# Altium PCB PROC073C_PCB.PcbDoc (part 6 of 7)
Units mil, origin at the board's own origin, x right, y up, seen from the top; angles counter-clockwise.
Board outline 2165.35 x 2695.12 mil, 8 copper layers (Top Layer, L2_GND, L3_SIGNAL 1, L4_SIGNAL 2, L5_SIGNAL 3, L6_SIGNAL 4, L7_GND, Bottom Layer), stack 55.9 mil thick; 393 components, 319 nets, 1311 pads, 1643 vias.
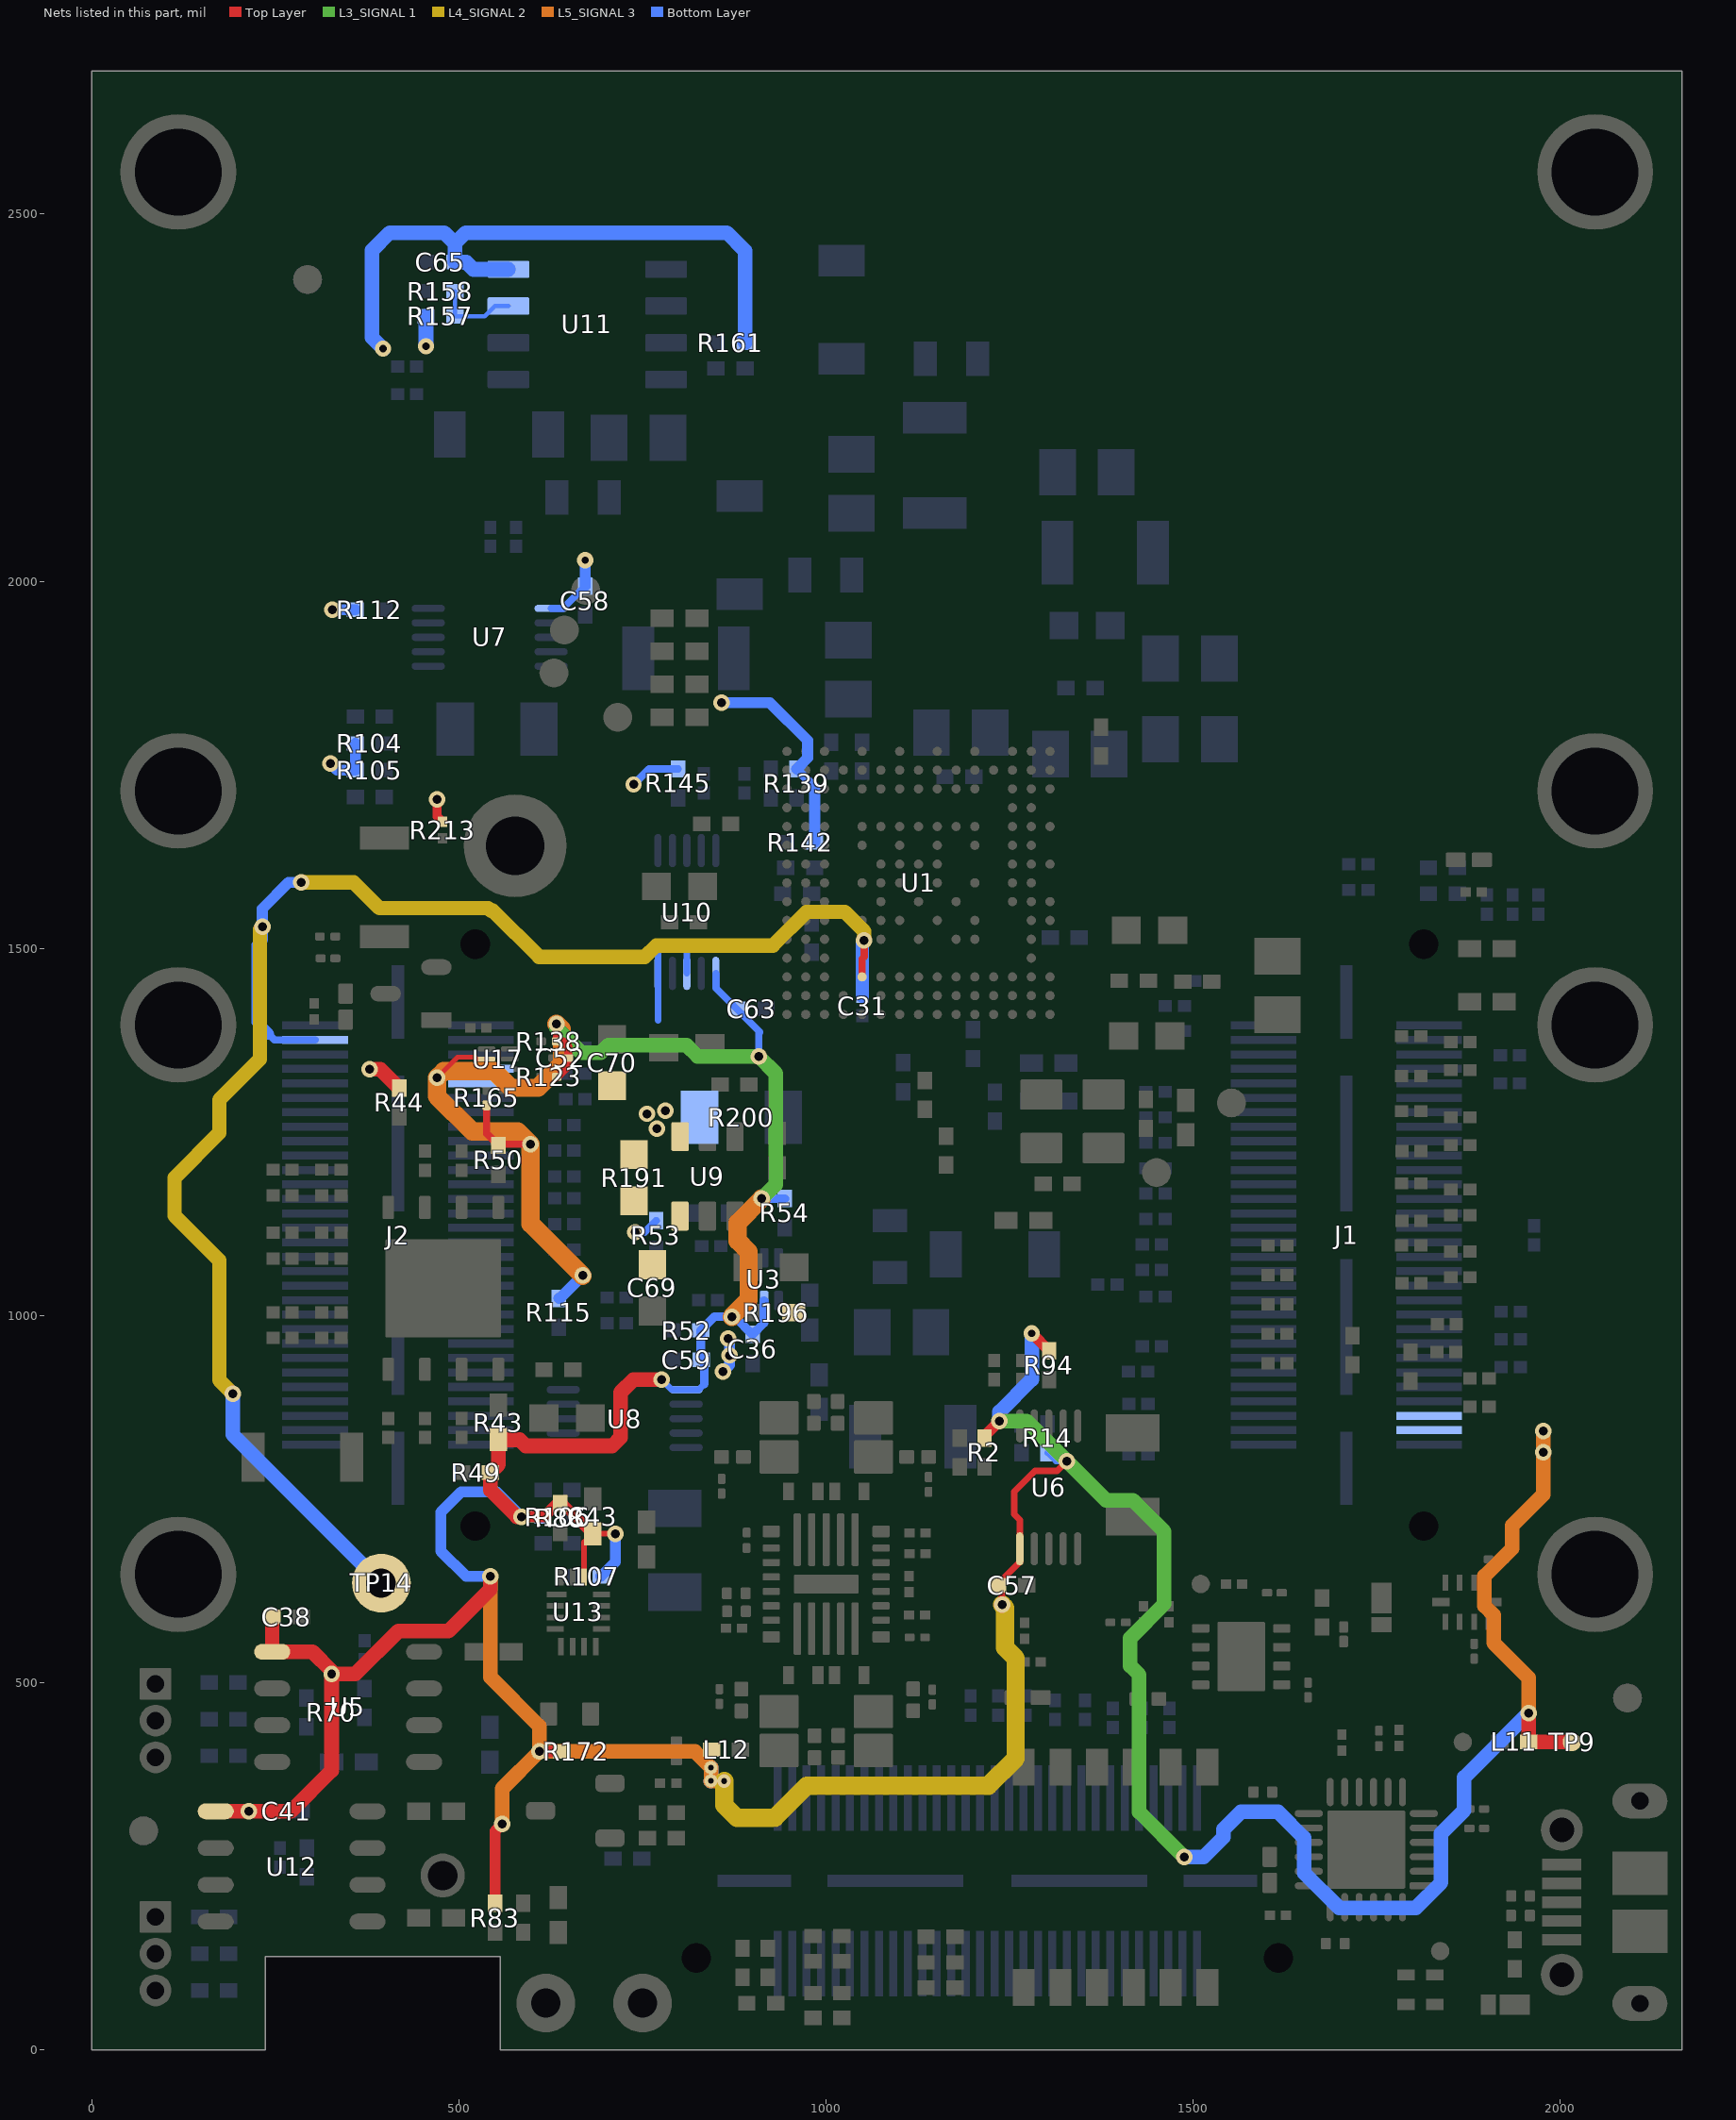
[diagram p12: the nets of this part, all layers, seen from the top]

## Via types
v1: diameter 13.77/15.74 (per signal layer), hole 5.9, Top Layer to L2_GND, tented both sides, 894 vias
v2: diameter 22.4, hole 12.2, Top Layer to Bottom Layer, tented both sides, 510 vias
v3: diameter 18, hole 8, Top Layer to Bottom Layer, tented both sides, 74 vias
v4: diameter 13.78/15.75 (per signal layer), hole 5.9, Top Layer to L2_GND, tented both sides, 72 vias
v5: diameter 22, hole 10, Top Layer to Bottom Layer, tented both sides, 61 vias
v6: diameter 19.68, hole 7.87, Top Layer to Bottom Layer, 16 vias
v7: diameter 13.77/15.74 (per signal layer), hole 5.9, Top Layer to L2_GND, tented top, 14 vias
v8: diameter 20, hole 10, Top Layer to Bottom Layer, tented both sides, 1 vias
v9: diameter 13.78/15.75 (per signal layer), hole 5.9, Top Layer to L2_GND, tented top, 1 vias

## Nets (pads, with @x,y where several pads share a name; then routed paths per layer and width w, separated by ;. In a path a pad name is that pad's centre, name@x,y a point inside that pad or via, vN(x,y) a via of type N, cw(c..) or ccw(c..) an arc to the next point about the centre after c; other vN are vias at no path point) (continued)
VCC_3V3: C36.2 C38.2 C41.2 C43.1 C52.2 C57.2 C58.2 C59.2 C63.2 C65.2 C69.1 J1.4 J1.6 J2.52 J2.54 L11.2 L12.1 R2.2 R14.2 R43.2 R44.2 R49.2 R50.1 R52.2 R53.2 R54.2 R70.1 R83.1 R88.2 R94.1 R104.2 R105.2 R106.2 R107.2 R112.1 R115.1 R123.1 R138.1 R139.2 R142.2 R145.1 R157.2 R161.2 R165.2 R172.2 R191.1 R213.2 TP9.1 U3.5 U5.5 U6.6 U7.6 U8.6 U9.1 U10.6 U11.8 U12.5 U13.14 U17.5 | length 9653.8
  Top Layer w6.69: v2(470.39,1323.91) 498.37,1351.89 521.97,1351.89 524.39,1349.48 U17.5@537.82,1349.48
  Top Layer w8: U13.14@670.66,644.19 670.66,691.58 C43.1@682.22,703.14 v2(713.13,703.14)
  Top Layer w9: v2(1239.72,606.43) 1239.72,626.9 C57.2@1233.87,632.76 1233.87,634.72 1263.99,664.84 U6.6@1263.99,682.61 1263.99,721.88 1256.27,729.6 1256.27,760.22 1284.73,788.68 1314.98,788.68 v2(1328.18,801.88)
  Top Layer w10: R165.2@537.82,1286.41 537.82,1247.93 R50.1@553.88,1231.88 555.61,1233.6 v2(597.7,1233.6)
  Top Layer w10.73: R123.1@633.25,1325.33 634.6,1325.33 649.03,1339.76 C52.2@649.03,1351.06 649.03,1367.16 642.57,1373.63 R138.1@633.25,1373.63 v2(633.25,1397.29)
  Top Layer w12: v2(470.62,1702.99) 470.62,1679.61 R213.2@477.94,1672.29
  Top Layer w15: R83.1@549.57,199.85 549.57,298.28 v2(559.11,307.82) ; v2(585.46,726.36) 615.64,726.36 633.67,744.38 R88.2@638.24,744.38 640.98,744.38 C43.1@682.22,703.14 ; v2(609.66,406.64) R172.2@640.13,406.64 ; R2.2@1214.31,833.59 1214.31,834.82 v2(1236.22,856.73) ; v5(1280.29,976.03) R94.1@1303.87,952.45
  Top Layer w19: U5.5@245.94,542.41 C38.2@245.94,589.74
  Top Layer w19.68: v2(1956.87,459.05) L11.2@1956.87,419.58 TP9.1@2015.61,419.58
  Top Layer w20: U12.5@169.09,325.13 v2(213.91,325.13) 271.3,325.13 326.89,380.72 v2(326.89,512.16) ; U5.5@245.94,542.41 300.81,542.41 326.89,516.33 v2(326.89,512.16) ; v2(378.7,1335.67) 393.13,1335.67 R44.2@418.88,1309.92 ; 542.96,762.7 543.25,762.42 ; v2(543.21,644.96) 543.21,627.89 486,570.68 417.69,570.68 359.17,512.16 v2(326.89,512.16) ; v2(585.46,726.36) 579.31,726.36 543.25,762.42 ; v2(776.27,913.04) 737.86,913.04 720.4,895.58 720.4,834.32 708.88,822.81 591.27,822.81 582.91,831.17 R43.2@553.88,831.17 553.88,797.27 R49.2@543.25,786.64 543.25,762.42
  L3_SIGNAL 1 w20: v2(633.25,1397.29) 633.25,1391.6 666.6,1358.24 693.11,1358.24 703.37,1368.5 809.96,1368.5 825.28,1353.18 v2(908.42,1353.18) 931.64,1329.96 931.64,1178.67 v2(912.43,1159.45) ; v2(1236.22,856.73) 1273.33,856.73 v2(1328.18,801.88) 1381.27,748.78 1417.89,748.78 1460.54,706.14 1460.54,607.41 1414.21,561.09 1414.21,523.36 1426.49,511.08 1426.49,324.24 v2(1487.9,262.82)
  L5_SIGNAL 3 w20: v2(543.21,644.96) 543.21,507.66 609.66,441.21 v2(609.66,406.64) ; v2(559.11,307.82) 559.11,356.09 v2(609.66,406.64) ; v3(843.24,366.57) v3@843.42,366.39 ; v3(861.42,366.39) v3@843.42,366.39 ; v2(1956.87,459.05) 1956.87,506.92 1909.31,554.48 1909.31,592.36 1896.69,604.98 1896.69,645.5 1934.57,683.39 1934.57,714.47 1976.48,756.38 v2(1976.48,813.88) v2(1976.48,842.87) ; v2(609.66,406.64) 821.54,406.64 v3(843.42,384.76) v3@843.42,366.39
  L5_SIGNAL 3 w25: v2(633.25,1397.29) 640.36,1390.18 640.36,1342.9 607.75,1310.29 571.09,1310.29 548.34,1333.04 479.52,1333.04 v2(470.39,1323.91) 470.39,1298.97 518.3,1251.06 580.24,1251.06 v2(597.7,1233.6) 597.7,1125.23 v2@668.45,1054.48 ; v2(871.67,998.68) 894.73,1021.74 894.73,1087.03 879.76,1102 879.76,1126.79 v2(912.43,1159.45)
  L4_SIGNAL 2 w25: v3(861.42,366.39) 861.42,333.66 878.85,316.23 930.21,316.23 974.02,360.04 1221.23,360.04 1258.27,397.08 1258.27,533.53 1243.94,547.87 1243.94,602.21 v2(1239.72,606.43)
  Bottom Layer w8: R14.2@1301.47,813.46 1313.05,801.88 v2(1328.18,801.88)
  Bottom Layer w9: v2(776.27,913.04) 790.04,899.27 U8.6@809.52,899.27 826.62,899.27 834.38,907.03
  Bottom Layer w9.84: U7.6@625.74,1963.11 641.76,1963.11 C58.2@672.08,1993.43
  Bottom Layer w10: v2(738,1723.37) 759.09,1744.45 R145.1@798.74,1744.46 ; v2(740.28,1113.77) 753.05,1113.77 R53.2@768.74,1129.46 ; U10.6@849.96,1466.11 849.96,1446.18 909.87,1386.27 908.42,1384.82 v2(908.42,1353.18)
  Bottom Layer w12: 834.38,907.03 834.38,935.7 C59.2@830,940.08 829.62,940.47 R52.2@829.62,980.11 848.19,998.68 v2(871.67,998.68) 875.77,998.68 C36.2@900,974.46 915.74,990.2 U3.5@915.74,1020.64 ; v2(912.43,1159.45) R54.2@943.74,1159.46 ; R139.2@960,1744.46 984.68,1719.77
  Bottom Layer w15: v2(213.91,325.13) C41.2@245.95,325.13 ; v2(325.17,1751.87) 334.15,1742.89 R105.2@359.16,1742.89 R104.2@359.16,1779.32 ; R70.1@326.89,479.59 v2(326.89,512.16) ; v2(327.89,1961.46) R112.1@359.16,1961.46 ; v2(543.21,644.96) 510.06,644.96 475.58,679.45 475.58,732.68 503.05,760.16 551.66,760.16 v2(585.46,726.36) R106.2@614.95,726.36 ; R115.1@636.16,1023.72 637.69,1023.72 v2(668.74,1054.77) ; C58.2@672.08,1993.43 v5(672.07,2028.74) ; R107.2@693.69,645.31 713.13,664.75 v2(713.13,703.14) ; v2(858,1834.77) 923.52,1834.77 975,1783.29 975,1759.45 R139.2@960,1744.46 ; R142.2@984.69,1644.77 984.68,1719.77
  Bottom Layer w20: v5(397,2316.77) 382,2331.77 382,2450.77 406,2474.77 480,2474.77 494.68,2460.08 ; v5(455.31,2320.08) R157.2@455.31,2360.77 ; U11.8@567.72,2424.77 520,2424.77 510,2434.77 C65.2@494.69,2434.77 494.68,2460.08 ; v3(843.24,366.57) 843.42,366.76 v3(843.42,384.76) ; R161.2@889.69,2324.77 889.68,2450.08 865,2474.77 509.37,2474.77 494.68,2460.08 ; v2(1236.22,856.73) 1236.22,869.08 1280.29,913.15 v5(1280.29,976.03) ; v2(1487.9,262.82) 1514.1,262.82 1541.5,290.22 1541.5,300.97 1564.9,324.38 1615.68,324.38 1650.86,289.19 1650.86,241.44 1698.72,193.59 1803,193.59 1837.58,228.17 1837.58,295.04 1869.09,326.55 1869.09,371.27 v2(1956.87,459.05)
VCC_LD_SW_3V3: C70.1 R191.2 R196.1 R200.1 U9.6 U10.8 U10.10 | length 224.1
  Bottom Layer w9: 771.22,1402.29 771.22,1497.77 781.22,1507.77 800.59,1507.77 810.59,1497.77 U10.8@810.59,1466.11
  Bottom Layer w15: v2(859.91,924.18) 868.76,933.03 v2(868.76,946.07) 868.76,966.98 v2(866.76,968.98)
  other v2: 770.05,1254.92 756.37,1274.97 781.23,1279.16
VPP_1P7: C31.2 J2.57 TP14.1 U1.L13 | length 2359.6
  Top Layer w10: U1.L13@1049.21,1461.43 1049.2,1486.11 1052.02,1488.93 v2(1052.02,1510.83)
  L4_SIGNAL 2 w19.68: v2(192.29,893.92) 173.92,912.28 173.92,1075.37 112.96,1136.33 112.96,1187.91 174.08,1249.03 174.08,1294.08 229.24,1349.25 229.24,1526.15 v2(232.52,1529.42) ; v2(285.39,1589.94) 357.04,1589.94 391.91,1555.06 540.25,1555.06 544.01,1551.31 546.65,1551.31 609.38,1488.58 753.41,1488.58 768.79,1503.96 927.62,1503.96 973.49,1549.83 1025.65,1549.83 1052.02,1523.45 v2(1052.02,1510.83)
  Bottom Layer w10: 241.12,1383.64 249.25,1375.52 J2.57@304.44,1375.52
  Bottom Layer w15: 241.12,1383.64 225,1399.77 225,1504.52 232.52,1512.04 v2(232.52,1529.42) 232.52,1554.21 268.24,1589.94 v2(285.39,1589.94)
  Bottom Layer w18: C31.2@1049.59,1434.76 1049.59,1508.39 v2(1052.02,1510.83)
  Bottom Layer w19.68: v2(192.29,893.92) 192.29,838.15 TP14.1@394.54,635.9
WP#: R157.1 R158.2 U11.7 | length 112.8
  Bottom Layer w6: R158.2@494.69,2394.77 R157.1@494.69,2360.77 535.43,2360.77 549.43,2374.77 U11.7@567.72,2374.77
pads on no net: FID1.1 FID2.1 FID3.1 FID4.1 FID5.1 FID6.1 J1.MH1 J1.MH2 J2.1 J2.2 J2.3 J2.4 J2.5 J2.6 J2.7 J2.8 J2.9 J2.10 J2.11 J2.12 J2.13 J2.14 J2.15 J2.16 J2.17 J2.18 J2.20 J2.22 J2.24 J2.26 J2.33 J2.35 J2.45 J2.47 J2.49 J2.51 J2.53 J2.55 J2.MH1 J2.MH2 J5.4 J6.4 J6.5 J6.6 J6.8 J6.14 J6.MH1 J6.MH2 LBL1.0 S1.6 S1.7 U2. U4. U11.1 U11.2 U14.10 U14.11 U14.14 U14.15 U14.16 U14.18 U14.19 U14.21 U14.22 U14.23 U14.24 U16.9@1565.44,511.07 U16.9@1565.44,560.68

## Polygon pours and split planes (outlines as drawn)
CONN_5V on Top Layer "CONN_5V_L01_P22319" (solid, remove dead copper, pour order 22319): 1077.37,317.76 1077.37,238.83 1095.58,220.62 1195.72,220.62 1251.48,164.86 1330.58,164.86 1380.08,115.35 1564.44,115.35 1604.25,155.16 1604.25,303.71 1570.7,337.26 1096.88,337.26
GND on Top Layer "GND_L01_P448" (solid, remove dead copper, pour order 22323): 33 vertices, not listed, extent 31,1503.77 2140,2673.82
GND on Top Layer "GND_L01_P22314" (solid, remove dead copper, pour order 22314): 27 vertices, not listed, extent 1134.79,431.41 1441.31,573.12
GND on Top Layer "TOP-No Net 1" (solid, remove dead copper, pour order 22322): 170,1130.18 160.59,1120.77 160.59,1101.95 170,1092.54 170,1013.41 170,737.08 207.5,699.58 207.5,557.27 200,549.78 30,549.95 30,2673.77 226,2673.77 226,1345.74 170,1289.74
RADAR_1V8 on Top Layer "RADAR_1V8_L01_P22244" (solid, remove dead copper, pour order 22244): 1031.46,939.5 1031.46,910.86 1036.01,906.31 1064.23,906.31 1069.98,912.06 1069.98,939.16 1065.03,944.12 1036.08,944.12
GND on Top Layer "TOP-No Net" (solid, remove dead copper, pour order 22320): 848.74,2673.73 667.78,2674.08 667.7,2057.81 727.62,1997.88 846.06,1997.88 848.74,2000.56
VCC_3V3 on Top Layer "TOP-No Net 1" (solid, remove dead copper, pour order 22311): 740.77,1036.27 779.97,1036.27 789.32,1045.61 789.32,1087.29 810.15,1108.12 816.25,1114.22 816.25,1154.98 791.46,1179.77 713.74,1179.77 713.74,1132.51 655.74,1074.5 655.74,1051.76 671.24,1036.26
RADAR_1V2 on Top Layer "TOP-No Net 1" (solid, remove dead copper, pour order 22293): 830.93,1414.77 860.59,1414.77 910.59,1364.77 955.59,1364.77 970.59,1349.77 970.59,1339.77 930.59,1299.77 885.59,1299.77 885.59,1334.76 875.59,1344.77 825.59,1344.77 820.59,1349.77 820.59,1404.43
GND on Top Layer " " (solid, remove dead copper, pour order 22284): 1018.78,524.15 1018.78,486.16 1030.58,474.37 1030.58,421.98 1024.32,415.72 975.98,415.72 971.57,420.14 971.57,472.14 982.09,482.66 982.09,523.95
5V_IN on Top Layer "5V_IN_L01_P22275" (solid, remove dead copper, pour order 22275): 17 vertices, not listed, extent 1251.55,516.39 1324.77,627.46
CB_PMIC_1V0 on Top Layer "CB_PMIC_1V0_L01_P22270" (solid, remove dead copper, pour order 22270): 1624.12,814.83 1575.25,814.83 1566.77,806.36 1566.77,770.14 1573.56,763.36 1623.52,763.36 1629.24,769.07 1629.24,809.7
CB_PMIC_1V2 on Top Layer "CB_PMIC_1V2_L01_P22268" (solid, remove dead copper, pour order 22268): 776.93,539.06 776.93,571.14 787.55,581.75 821.54,581.75 831.08,572.22 831.08,537.91 821.08,527.91 805.3,527.91 800.52,532.69 783.3,532.69
PMIC_1V2 on Top Layer "PMIC_1V2_L01_P22260" (solid, remove dead copper, pour order 22260): 731.77,764.34 723.76,772.35 723.76,794.24 740.26,810.74 774.84,810.74 781.89,803.69 781.89,785.03 761.2,764.34
RADAR_3V3 on Top Layer "RADAR_3V3_L01_P220" (solid, remove dead copper, pour order 22285): 815,1604.77 815,1524.77 820,1519.77 900,1519.77 905,1524.77 905,1539.77 890,1554.77 885,1554.77 865,1574.77 865,1594.77 855,1604.77
NetR214_1 on Top Layer "NETR214_1_L01_P22303" (solid, remove dead copper, pour order 22303): 428.73,1557.47 340.26,1557.47 324.8,1542.01 324.8,1471.04 332.41,1463.43 423.15,1463.43 453.32,1493.6 453.32,1532.88
CONN_5V on Top Layer "CONN_5V_L01_P22246" (solid, remove dead copper, pour order 22246): 1376.03,584.14 1373.52,581.63 1373.52,531.29 1378.52,526.29 1393,526.29 1398.96,532.25 1398.96,587.59 1395.12,591.44 1383.32,591.44
CONN_5V on Top Layer "CONN_5V_L01_P22274" (solid, remove dead copper, pour order 22274): 1605.95,570.98 1605.95,667.7 1616.86,678.6 1640.56,678.6 1656.71,662.46 1656.71,639.97 1637.57,620.84 1637.57,600.12 1632.56,595.11 1632.56,569.45 1630.35,567.25 1609.69,567.25
5V_IN_SW on Top Layer "5V_IN_SW_L01_P22289" (solid, remove dead copper, pour order 22289): 21 vertices, not listed, extent 1601.18,521.25 1739.18,601.39
NetD2_2 on Top Layer "NETD2_2_L01_P22292" (solid, remove dead copper, pour order 22292): 1656.71,629.15 1696.47,668.92 1770.38,668.92 1781.63,657.67 1781.63,602.91 1774.29,595.58 1741.54,595.58 1734.2,602.91 1663.55,602.91 1656.71,609.76
PMICOUT_3V3 on Top Layer "PMICOUT_3V3_L01_P22317" (solid, remove dead copper, pour order 22317): 26 vertices, not listed, extent 1236.39,339.84 1741.42,493.28
GND on Top Layer "GND_L01_P22304" (solid, remove dead copper, pour order 22304): 17 vertices, not listed, extent 902.3,105.41 1002.96,254.25
5V_IN on Top Layer "5V_IN_L01_P22283" (solid, remove dead copper, pour order 22283): 1781.52,590.62 1737.87,590.62 1722.9,575.65 1722.9,524.58 1736.24,511.24 1779.35,511.24 1791.8,523.7 1791.8,580.34
5V_IN_USB on Top Layer "5V_IN_USB_L01_P22276" (solid, remove dead copper, pour order 22276): 18 vertices, not listed, extent 1602.23,459.15 1722.05,532.03
PMIC_3V3 on Top Layer "Bottom Layer-PMIC_3V3" (solid, pour order 22306): 871.36,389.15 880.03,380.48 880.03,333.59 883.52,330.1 963.71,330.1 995.6,361.99 995.6,432.05 871.36,432.05
CB_PMIC_1V8 on Top Layer "CB_PMIC_1V8_L01_P22288" (solid, remove dead copper, pour order 22288): 937.54,1087.93 990.48,1087.93 999.69,1097.14 1033.26,1097.14 1040.77,1089.63 1040.77,1041.71 1025.44,1026.37 996.45,1026.37 980.42,1042.4 936.76,1042.4 933.18,1045.98 933.18,1083.57
VCC_LD_SW_3V3 on Top Layer "VCC_LD_SW_3V3_L01_P22294" (solid, remove dead copper, pour order 22294): 936.29,1023.35 936.29,999.84 917.45,981 853.41,981 848.47,976.06 848.47,917.08 857.82,907.73 875.53,907.73 890.04,922.24 907.46,939.66 961.46,939.66 985.9,964.11 985.9,1026.72 979.93,1032.7 945.63,1032.7
PMIC_1V8 on Top Layer "PMIC_1V8_L01_P22312" (solid, remove dead copper, pour order 22312): 17 vertices, not listed, extent 1289.77,606.39 1467.93,755.32
VCC_LD_SW_3V3 on Top Layer "TOP-No Net 1" (solid, remove dead copper, pour order 22308): 691.74,1335.77 767.73,1335.77 813.74,1289.77 813.74,1224.77 788.74,1199.77 718.74,1199.77 708.74,1209.77 708.74,1245.77 686.74,1267.77 686.74,1330.77
RADAR_3V3 on Top Layer "RADAR_3V3_L01_P210" (solid, remove dead copper, pour order 22269): 1102.98,1262.77 1157,1262.77 1169,1262.77 1174,1257.77 1174,1235.77 1171,1232.76 1148,1232.77 1133.18,1217.94 1111.82,1217.94 1094,1235.77 1094,1253.78
5V_IN on Top Layer "Bottom Layer-5V_IN 4" (solid, pour order 22250): 916.33,779.48 916.33,738.48 956.33,738.48 958.33,740.48 958.33,776.48 955.33,779.48
GND on Top Layer "TOP-No Net 11" (solid, remove dead copper, pour order 22296): 94 vertices, not listed, extent 996.99,1979.09 1095.41,2452.08
PMIC_1V0 on Top Layer "Bottom Layer-PMIC_1V0 1" (solid, pour order 22307): 960.52,839.43 960.52,871.68 994.13,871.68 994.13,931.27 847.15,931.27 847.15,839.43
5V_IN_USB on Top Layer "5V_IN_USB_L01_P22310" (solid, remove dead copper, pour order 22310): 1875.54,86.33 1880.49,81.38 1909.52,81.38 1921.49,69.42 1921.49,48.85 1900.75,28.12 1673.31,28.12 1662.82,38.61 1662.82,69.95 1703.04,110.18 1730.7,110.18 1754.55,86.33
PMICOUT_3V3 on Top Layer "PMICOUT_3V3_L01_P22315" (solid, remove dead copper, pour order 22315): 19 vertices, not listed, extent 1773.63,296.73 1930.87,488.17
CB_PMIC_1V8 on Top Layer "CB_PMIC_1V8_L01_P22318" (solid, remove dead copper, pour order 22318): 17 vertices, not listed, extent 1305.39,644.91 1729.65,918.05
GND on Top Layer "TOP-No Net 1" (solid, remove dead copper, pour order 22290): 707.44,1015.04 723.12,1030.72 789.62,1030.72 795.85,1024.49 795.85,967.98 775.02,947.16 720.05,947.16 707.44,959.76
VCC_3V3 on Top Layer " " (solid, remove dead copper, pour order 22261): 860.94,381.7 873.35,369.28 873.35,358.04 868.31,353 829.37,353 829.37,421.73 860.94,421.73
PMIC_1V2 on Top Layer "Bottom Layer-PMIC_1V2" (solid, pour order 22309): 1172.84,448.01 1172.84,359.84 1006.53,359.83 1006.53,448.01
5V_IN on Top Layer "Bottom Layer-5V_IN 1" (solid, pour order 22247): 916.33,528.98 916.33,487.98 956.33,487.98 958.33,489.98 958.33,525.98 955.33,528.98
5V_IN on Top Layer "Bottom Layer-5V_IN 3" (solid, pour order 22249): 1084.33,739.98 1084.33,780.98 1044.33,780.98 1042.33,778.98 1042.33,742.98 1045.33,739.98
5V_IN on Top Layer "Bottom Layer-5V_IN 2" (solid, pour order 22248): 1084.33,489.48 1084.33,530.48 1044.33,530.48 1042.33,528.48 1042.33,492.48 1045.33,489.48
PMIC_1V8 on Top Layer "Bottom Layer-PMIC_1V8" (solid, pour order 22313): 1004.7,885.77 1004.7,954.5 1020.66,970.46 1148.01,970.46 1163.6,954.87 1163.6,889.45 1163.6,837.48 1036.52,837.48 1036.52,870.9 1004.7,870.9
GND on Top Layer " " (solid, remove dead copper, pour order 22287): 1016.81,745.5 982.84,745.5 981.72,746.62 981.72,783.53 973.88,791.37 973.88,862.62 975.87,864.6 1025.45,864.6 1028.19,861.86 1028.19,790.2 1017.93,779.95 1017.93,747.74
PMICOUT_3V3 on Top Layer "PMICOUT_3V3_L01_P22286" (solid, remove dead copper, pour order 22286): 581,2045.4 581,1980.02 592.26,1968.76 629.35,1968.76 651.94,1991.35 651.94,2039.93 636.02,2055.85 591.45,2055.85
RADAR_1V8 on Top Layer "RADAR_1V8_L01_P222" (solid, remove dead copper, pour order 22291): 1572.86,1459.28 1575.38,1456.77 1587.99,1456.77 1590.66,1454.1 1637.41,1454.1 1648.54,1442.96 1648.54,1381.73 1643.18,1376.37 1578.77,1376.37 1555.96,1399.18 1555.96,1453.47 1561.77,1459.28
GND on Top Layer "TOP-No Net" (solid, remove dead copper, pour order 22316): 1976.7,2635.77 1976.77,2673.69 809.74,2673.83 809.74,2635.77
GND on Top Layer "TOP-No Net 17" (solid, remove dead copper, pour order 22297): 94 vertices, not listed, extent 1193.85,1979.09 1292.27,2452.08
GND on Top Layer "OUTLINE-No Net" (solid, remove dead copper, pour order 22259): 1787.47,2046.12 1787.47,1990.83 1805.98,1990.83 1805.98,1979.11 1821.73,1979.11 1821.73,2006.58 1803.22,2006.58 1803.22,2030.38 1821.73,2030.38 1821.73,2071.23 1805.98,2071.23 1805.98,2046.12 1787.47,2046.12
TX3 on Top Layer "TOP-RX1 72" (solid, pour order 22221): 1835.62,2249.46 1831.62,2249.46 1831.62,2188.91 1835.62,2188.91 1835.62,2249.46
GND on Top Layer "OUTLINE-No Net" (solid, remove dead copper, pour order 22255): 1894.77,2452.1 1772.47,2452.1 1772.47,2436.35 1894.77,2436.35 1894.77,2452.1
TX3 on Top Layer "TOP-RX1 73" (solid, pour order 22222): 1835.62,2358.05 1831.62,2358.05 1831.62,2297.49 1835.62,2297.49 1835.62,2358.05
GND on Top Layer "TOP-GND 25" (solid, remove dead copper, pour order 22239): 1894.77,2110.6 1845.52,2110.6 1845.52,2094.86 1894.77,2094.86
TX3 on Top Layer "TOP-RX1 74" (solid, pour order 22225): 1837.52,2071.23 1829.73,2071.23 1829.73,2033.05 1837.52,2033.05 1837.52,2071.23
GND on Top Layer "OUTLINE-No Net" (solid, remove dead copper, pour order 22241): 1821.73,2110.6 1772.47,2110.6 1772.47,2094.86 1821.73,2094.86 1821.73,2110.6
TX3 on Top Layer "TOP-RX1 75" (solid, pour order 22209): 1837.52,2033.05 1829.73,2033.05 1829.73,2018.48 1837.52,2018.48 1837.52,2033.05
GND on Top Layer "OUTLINE-No Net" (solid, remove dead copper, pour order 22236): 1821.73,2094.86 1805.98,2094.86 1805.98,2071.23 1821.73,2071.23 1821.73,2094.86
TX3 on Top Layer "TOP-RX1 76" (solid, pour order 22206): 1850.51,2036.94 1837.52,2036.94 1837.52,2029.15 1850.51,2029.15 1850.51,2036.94
GND on Top Layer "TOP-GND 26" (solid, remove dead copper, pour order 22234): 1861.27,2094.86 1845.52,2094.86 1845.52,2071.23 1861.27,2071.23 1861.27,2094.86
TX3 on Top Layer "TOP-RX1 77" (solid, pour order 22264): 1859.21,2188.91 1808.03,2188.91 1808.03,2140.88 1859.21,2140.88 1859.21,2188.91
GND on Top Layer "TOP-GND 27" (solid, remove dead copper, pour order 22251): 1861.27,2071.23 1845.52,2071.23 1845.52,2044.94 1858.51,2044.94 1858.51,2021.15 1845.52,2021.15 1845.52,1979.11 1861.27,1979.11 1861.27,2005.4 1874.26,2005.4 1874.26,2060.69 1861.27,2060.69 1861.27,2071.23
TX3 on Top Layer "TOP-RX1 78" (solid, pour order 22230): 1837.52,2110.6 1829.73,2110.6 1829.73,2071.23 1837.52,2071.23 1837.52,2110.6
TX3 on Top Layer "TOP-RX1 79" (solid, pour order 22213): 1835.62,2140.88 1831.62,2140.88 1831.62,2110.6 1835.62,2110.6 1835.62,2140.88
TX3 on Top Layer "TOP-RX1 80" (solid, pour order 22215): 1829.73,2022.38 1811.22,2022.38 1811.22,2014.58 1829.73,2014.58 1829.73,2022.38
TX3 on Top Layer "TOP-RX1 81" (solid, pour order 22271): 1871.02,2297.49 1796.22,2297.49 1796.22,2249.46 1871.02,2249.46 1871.02,2297.49
GND on Top Layer "OUTLINE-No Net" (solid, remove dead copper, pour order 22278): 1788.22,2436.35 1772.47,2436.35 1772.47,2110.6 1788.22,2110.6 1788.22,2436.35
TX3 on Top Layer "TOP-RX1 83" (solid, pour order 22263): 1859.21,2406.08 1808.03,2406.08 1808.03,2358.05 1859.21,2358.05 1859.21,2406.08
GND on Top Layer "OUTLINE-No Net" (solid, remove dead copper, pour order 22281): 1894.77,2436.35 1879.02,2436.35 1879.02,2110.6 1894.77,2110.6 1894.77,2436.35
GND on Top Layer "OUTLINE-No Net" (solid, remove dead copper, pour order 22282): 1697.92,2534.78 1682.17,2534.78 1682.17,2209.03 1697.92,2209.03 1697.92,2534.78
TX2 on Top Layer "TOP-RX1 83" (solid, pour order 22265): 1662.36,2504.5 1611.18,2504.5 1611.18,2456.47 1662.36,2456.47 1662.36,2504.5
GND on Top Layer "OUTLINE-No Net" (solid, remove dead copper, pour order 22277): 1591.37,2534.78 1575.62,2534.78 1575.62,2209.03 1591.37,2209.03 1591.37,2534.78
TX2 on Top Layer "TOP-RX1 81" (solid, pour order 22273): 1674.17,2395.92 1599.37,2395.92 1599.37,2347.89 1674.17,2347.89 1674.17,2395.92
TX2 on Top Layer "TOP-RX1 80" (solid, pour order 22214): 1632.88,2120.8 1614.37,2120.8 1614.37,2113.01 1632.88,2113.01 1632.88,2120.8
TX2 on Top Layer "TOP-RX1 79" (solid, pour order 22212): 1638.77,2239.3 1634.77,2239.3 1634.77,2209.03 1638.77,2209.03 1638.77,2239.3
TX2 on Top Layer "TOP-RX1 78" (solid, pour order 22228): 1640.67,2209.03 1632.88,2209.03 1632.88,2169.66 1640.67,2169.66 1640.67,2209.03
TX2 on Top Layer "TOP-RX1 77" (solid, pour order 22267): 1662.36,2287.34 1611.18,2287.34 1611.18,2239.3 1662.36,2239.3 1662.36,2287.34
GND on Top Layer "TOP-GND 26" (solid, remove dead copper, pour order 22233): 1664.42,2193.28 1648.67,2193.28 1648.67,2169.66 1664.42,2169.66 1664.42,2193.28
TX2 on Top Layer "TOP-RX1 76" (solid, pour order 22207): 1653.66,2135.37 1640.67,2135.37 1640.67,2127.57 1653.66,2127.57 1653.66,2135.37
GND on Top Layer "OUTLINE-No Net" (solid, remove dead copper, pour order 22235): 1624.88,2193.28 1609.13,2193.28 1609.13,2169.66 1624.88,2169.66 1624.88,2193.28
TX2 on Top Layer "TOP-RX1 75" (solid, pour order 22210): 1640.67,2131.47 1632.88,2131.47 1632.88,2116.9 1640.67,2116.9 1640.67,2131.47
GND on Top Layer "OUTLINE-No Net" (solid, remove dead copper, pour order 22238): 1624.88,2209.03 1575.62,2209.03 1575.62,2193.28 1624.88,2193.28 1624.88,2209.03
TX2 on Top Layer "TOP-RX1 74" (solid, pour order 22223): 1640.67,2169.66 1632.88,2169.66 1632.88,2131.47 1640.67,2131.47 1640.67,2169.66
GND on Top Layer "TOP-GND 25" (solid, remove dead copper, pour order 22240): 1697.92,2209.03 1648.67,2209.03 1648.67,2193.28 1697.92,2193.28 1697.92,2209.03
TX2 on Top Layer "TOP-RX1 73" (solid, pour order 22218): 1638.77,2456.47 1634.77,2456.47 1634.77,2395.92 1638.77,2395.92 1638.77,2456.47
GND on Top Layer "OUTLINE-No Net" (solid, remove dead copper, pour order 22254): 1697.92,2550.53 1575.62,2550.53 1575.62,2534.78 1697.92,2534.78 1697.92,2550.53
TX2 on Top Layer "TOP-RX1 72" (solid, pour order 22219): 1638.77,2347.89 1634.77,2347.89 1634.77,2287.34 1638.77,2287.34 1638.77,2347.89
GND on Top Layer "OUTLINE-No Net" (solid, remove dead copper, pour order 22258): 1393.77,2046.12 1393.77,1990.83 1412.28,1990.83 1412.28,1979.11 1428.02,1979.11 1428.02,2006.58 1409.52,2006.58 1409.52,2030.38 1428.02,2030.38 1428.02,2071.23 1412.28,2071.23 1412.28,2046.12 1393.77,2046.12
TX1 on Top Layer "TOP-RX1 72" (solid, pour order 22217): 1441.92,2249.46 1437.92,2249.46 1437.92,2188.91 1441.92,2188.91 1441.92,2249.46
GND on Top Layer "OUTLINE-No Net" (solid, remove dead copper, pour order 22256): 1501.07,2452.1 1378.77,2452.1 1378.77,2436.35 1501.07,2436.35 1501.07,2452.1
TX1 on Top Layer "TOP-RX1 73" (solid, pour order 22220): 1441.92,2358.05 1437.92,2358.05 1437.92,2297.49 1441.92,2297.49 1441.92,2358.05
GND on Top Layer "TOP-GND 25" (solid, remove dead copper, pour order 22242): 1501.07,2110.6 1451.82,2110.6 1451.82,2094.86 1501.07,2094.86 1501.07,2110.6
TX1 on Top Layer "TOP-RX1 74" (solid, pour order 22224): 1443.82,2071.23 1436.02,2071.23 1436.02,2033.05 1443.82,2033.05 1443.82,2071.23
GND on Top Layer "OUTLINE-No Net" (solid, remove dead copper, pour order 22243): 1428.02,2110.6 1378.77,2110.6 1378.77,2094.86 1428.02,2094.86 1428.02,2110.6
TX1 on Top Layer "TOP-RX1 75" (solid, pour order 22208): 1443.82,2033.05 1436.02,2033.05 1436.02,2018.48 1443.82,2018.48 1443.82,2033.05
GND on Top Layer "OUTLINE-No Net" (solid, remove dead copper, pour order 22232): 1428.02,2094.86 1412.28,2094.86 1412.28,2071.23 1428.02,2071.23 1428.02,2094.86
TX1 on Top Layer "TOP-RX1 76" (solid, pour order 22205): 1456.81,2036.94 1443.82,2036.94 1443.82,2029.15 1456.81,2029.15 1456.81,2036.94
GND on Top Layer "TOP-GND 26" (solid, remove dead copper, pour order 22237): 1467.57,2094.86 1451.82,2094.86 1451.82,2071.23 1467.57,2071.23 1467.57,2094.86
TX1 on Top Layer "TOP-RX1 77" (solid, pour order 22262): 1465.51,2188.91 1414.33,2188.91 1414.33,2140.88 1465.51,2140.88 1465.51,2188.91
GND on Top Layer "TOP-GND 27" (solid, remove dead copper, pour order 22252): 1467.57,2071.23 1451.82,2071.23 1451.82,2044.94 1464.81,2044.94 1464.81,2021.15 1451.82,2021.15 1451.82,1979.11 1467.57,1979.11 1467.57,2005.4 1480.56,2005.4 1480.56,2060.69 1467.57,2060.69 1467.57,2071.23
TX1 on Top Layer "TOP-RX1 78" (solid, pour order 22231): 1443.82,2110.6 1436.02,2110.6 1436.02,2071.23 1443.82,2071.23 1443.82,2110.6
TX1 on Top Layer "TOP-RX1 79" (solid, pour order 22211): 1441.92,2140.88 1437.92,2140.88 1437.92,2110.6 1441.92,2110.6 1441.92,2140.88
TX1 on Top Layer "TOP-RX1 80" (solid, pour order 22216): 1436.02,2022.38 1417.52,2022.38 1417.52,2014.58 1436.02,2014.58 1436.02,2022.38
TX1 on Top Layer "TOP-RX1 81" (solid, pour order 22272): 1477.32,2297.49 1402.52,2297.49 1402.52,2249.46 1477.32,2249.46 1477.32,2297.49
GND on Top Layer "OUTLINE-No Net" (solid, remove dead copper, pour order 22279): 1394.52,2436.35 1378.77,2436.35 1378.77,2110.6 1394.52,2110.6 1394.52,2436.35
TX1 on Top Layer "TOP-RX1 83" (solid, pour order 22266): 1465.51,2406.08 1414.33,2406.08 1414.33,2358.05 1465.51,2358.05 1465.51,2406.08
GND on Top Layer "OUTLINE-No Net" (solid, remove dead copper, pour order 22280): 1501.07,2436.35 1485.32,2436.35 1485.32,2110.6 1501.07,2110.6 1501.07,2436.35
GND on Top Layer "TOP-No Net 10" (solid, remove dead copper, pour order 22295): 94 vertices, not listed, extent 1095.42,1979.09 1193.84,2452.08
GND on Top Layer "TOP-No Net 23" (solid, remove dead copper, pour order 22305): 125 vertices, not listed, extent 891.67,1979.09 996.98,2452.08
GND on Top Layer "TOP-No Net 24" (solid, pour order 22245): 35 vertices, not listed, extent 1292.28,2094.9 1299.17,2452.08
RX1 on Top Layer "TOP-No Net 43" (solid, remove dead copper, pour order 22301): 38 vertices, not listed, extent 910.37,1979.09 985.17,2406.06
RX2 on Top Layer "TOP-No Net 42" (solid, remove dead copper, pour order 22299): 38 vertices, not listed, extent 1008.8,1979.09 1083.6,2406.06
RX3 on Top Layer "TOP-No Net 41" (solid, remove dead copper, pour order 22300): 38 vertices, not listed, extent 1107.23,1979.09 1182.03,2406.06
RX4 on Top Layer "TOP-No Net 40" (solid, remove dead copper, pour order 22298): 38 vertices, not listed, extent 1205.66,1979.09 1280.46,2406.06
TX1 on Top Layer "TOP-RX1 82" (solid, remove dead copper, pour order 22229): 1443.82,2018.48 1436.02,2018.48 1436.02,1979.11 1443.82,1979.11 1443.82,2018.48
GND on Top Layer "OUTLINE-No Net" (solid, remove dead copper, pour order 22257): 1590.62,2144.55 1590.62,2089.26 1609.13,2089.26 1609.13,2077.53 1624.88,2077.53 1624.88,2105.01 1606.37,2105.01 1606.37,2128.8 1624.88,2128.8 1624.88,2169.66 1609.13,2169.66 1609.13,2144.55 1590.62,2144.55
GND on Top Layer "TOP-GND 27" (solid, remove dead copper, pour order 22253): 1664.42,2169.66 1648.67,2169.66 1648.67,2143.37 1661.66,2143.37 1661.66,2119.57 1648.67,2119.57 1648.67,2077.53 1664.42,2077.53 1664.42,2103.82 1677.41,2103.82 1677.41,2159.12 1664.42,2159.12 1664.42,2169.66
TX2 on Top Layer "TOP-RX1 82" (solid, remove dead copper, pour order 22226): 1640.67,2116.9 1632.88,2116.9 1632.88,2077.53 1640.67,2077.53 1640.67,2116.9
TX3 on Top Layer "TOP-RX1 82" (solid, remove dead copper, pour order 22227): 1837.52,2018.48 1829.73,2018.48 1829.73,1979.11 1837.52,1979.11 1837.52,2018.48
RADAR_VOUT_PA on Top Layer "TOP-No Net 1" (solid, remove dead copper, pour order 22302): 17 vertices, not listed, extent 1271.59,1735.77 1484.59,1849.77
GND on Top Layer "TOP-No Net" (solid, remove dead copper, pour order 22321): 1940.79,2673.65 2139.97,2674.05 2140.06,1916.77 1940.79,1916.76
GND on L3_SIGNAL 1 "GND_L03_P3050" (solid, remove dead copper, pour order 22329): 1013.99,1633.78 1079,1568.77 1079,1546.21 1166.44,1458.77 1315,1458.77 1399,1542.77 1619.2,1542.77 1710,1633.57 1710,1951.77 1620,2041.77 1089,2041.77 1013.99,1966.76
RADAR_1V2 on L3_SIGNAL 1 "RADAR_1V2_L03_P2940" (solid, remove dead copper, pour order 22327): 18 vertices, not listed, extent 662.15,1333.29 1182.6,2011.77
5V_IN on L3_SIGNAL 1 "5V_IN_L03_P22328" (solid, remove dead copper, pour order 22328): 1642.6,703.75 1809.3,870.44 1928.77,870.44 1957.87,841.34 1957.87,550.26 1982.89,525.25 2030.98,525.25 2097.36,458.88 2097.36,86.6 2030.42,19.66 1682.03,19.66 1642.6,59.09
5V_IN on L3_SIGNAL 1 "5V_IN_L03_P22326" (solid, remove dead copper, pour order 22326): 1104.05,800.65 1178.88,800.65 1283.63,695.9 1320.16,659.37 1320.16,553.76 1239.83,473.43 934.33,473.43 912.61,495.15 912.61,770.58 942.68,800.65
GND on L3_SIGNAL 1 "RADAR_1V8_L01_P-001" (solid, remove dead copper, pour order 22331): 25 vertices, not listed, extent 30,549.63 2140,2673.77
CB_PMIC_1V2 on L3_SIGNAL 1 "CB_PMIC_1V2_L03_P22330" (solid, remove dead copper, pour order 22330): 34 vertices, not listed, extent 229.92,488.7 908.93,2369.41
CONN_5V on L3_SIGNAL 1 "CONN_5V_L03_P22325" (solid, remove dead copper, pour order 22325): 897.63,88.44 897.63,127.1 729.1,295.63 660.14,295.63 626.99,262.49 626.99,41.5 652.99,15.51 824.7,15.51
GND on L5_SIGNAL 3 "GND_L05_P22338" (solid, remove dead copper, pour order 22338): 42 vertices, not listed, extent 1148.42,27.25 1866.73,1408.39
5V_IN_USB on L5_SIGNAL 3 "5V_IN_USB_L05_P22336" (solid, remove dead copper, pour order 22336): 1569.35,26.26 1569.35,384.02 1643.42,458.09 1643.42,478.44 1682.03,517.05 1682.03,582.2 1738.13,638.3 1844.76,638.3 1893.66,589.39 1893.66,576.15 1893.66,62.25 1857.66,26.26
GND on L5_SIGNAL 3 "BOTTOM-No Net" (solid, remove dead copper, pour order 22342): 31 vertices, not listed, extent 30,549.77 2140,2673.77
RADAR_1V8 on L5_SIGNAL 3 "RADAR_1V8_L04_P3008" (solid, remove dead copper, pour order 22337): 23 vertices, not listed, extent 882.64,1354.77 1582.52,1814.95
5V_IN on L5_SIGNAL 3 "5V_IN_L05_P22341" (solid, remove dead copper, pour order 22341): 23 vertices, not listed, extent 589.92,23.49 1602.31,624.2
PMIC_1V0 on L5_SIGNAL 3 "PMIC_1V0_L04_P2966" (solid, remove dead copper, pour order 22334): 681.23,1491.64 681.23,1835.66 653.12,1863.77 570.19,1863.77 493.58,1863.77 379.33,1749.52 379.32,1374.27 437.18,1316.42 648.32,1316.42 718.63,1386.73 718.63,1454.25
VCC_3V3 on L5_SIGNAL 3 "VCC_3V3_L04_P2992" (solid, remove dead copper, pour order 22339): 490.76,1872.91 635.08,1872.91 642.16,1865.83 642.16,1728.22 677.33,1693.05 822.28,1693.05 850.28,1693.05 891.28,1734.04 891.28,2248.57 802,2338.77 328,2338.77 261,2271.77 261,1770 293.01,1737.99 355.84,1737.99
CB_PMIC_1V8 on L5_SIGNAL 3 "CB_PMIC_1V8_L05_P22335" (solid, remove dead copper, pour order 22335): 35 vertices, not listed, extent 895.66,632.16 1700.13,1106.65
RADAR_1V2 on L5_SIGNAL 3 "RADAR_1V2_L05_P22333" (solid, remove dead copper, pour order 22333): 21 vertices, not listed, extent 767.92,1324.1 1039.56,1706.57
CONN_5V on L5_SIGNAL 3 "CONN_5V_L05_P22340" (solid, remove dead copper, pour order 22340): 30 vertices, not listed, extent 162.19,153.41 712.31,1523.69
PMIC_1V0 on L5_SIGNAL 3 "PMIC_1V0_L05_P22332" (solid, remove dead copper, pour order 22332): 1048.57,801.11 1041.25,793.8 1041.25,724.26 1008.83,691.84 862.05,691.84 842.56,711.33 842.56,883.58 884.58,925.6 955.79,925.6 970.91,910.48 970.91,893.47 999.43,864.95 1024.43,864.95 1048.57,840.81
5V_IN_USB on Bottom Layer "5V_IN_USB_L08_P22366" (solid, remove dead copper, pour order 22366): 17 vertices, not listed, extent 1670.87,460.03 1717.09,505.28
5V_IN on Bottom Layer "5V_IN_L08_P22397" (solid, remove dead copper, pour order 22397): 23 vertices, not listed, extent 1264.99,365.62 1804.75,710.07
CONN_5V on Bottom Layer "TOP-No Net 1" (solid, remove dead copper, pour order 22396): 20 vertices, not listed, extent 241,1369.77 632.12,1667.99
RADAR_3V3 on Bottom Layer "RADAR_3V3_L06_P386" (solid, remove dead copper, pour order 22398): 44 vertices, not listed, extent 687.41,1135.39 1299.98,1569.77
CB_PMIC_1V0 on Bottom Layer "CB_PMIC_1V0_L06_P422" (solid, remove dead copper, pour order 22395): 26 vertices, not listed, extent 745.55,1979.09 1168.35,2350.09
GND on Bottom Layer "TOP-No Net 1" (solid, remove dead copper, pour order 22403): 31,2400.77 228,2400.77 300,2472.77 2134,2472.77 2140,2478.77 2140,2673.77 30,2673.77 30,2399.77
NetJ6_1 on Bottom Layer "NETJ6_1_L08_P22399" (solid, remove dead copper, pour order 22399): 20 vertices, not listed, extent 562.78,40.45 962.37,481.12
CONN_5V on Bottom Layer "TOP-No Net 1" (solid, remove dead copper, pour order 22391): 18 vertices, not listed, extent 1608.12,622.7 1881.08,829.77
5V_IN_SW on Bottom Layer "5V_IN_SW_L08_P22380" (solid, remove dead copper, pour order 22380): 1541.1,622.4 1541.1,595.01 1550.4,585.71 1579.64,585.71 1631.52,533.84 1692.89,533.84 1720.37,561.31 1725.89,561.31 1736.76,572.18 1736.76,585.71 1712.31,610.16 1622.48,610.16 1601.81,630.82 1549.52,630.83
PMIC_1V2 on Bottom Layer "PMIC_1V2_L08_P22368" (solid, remove dead copper, pour order 22368): 1166.07,444.94 1107.8,444.94 1102.49,439.62 1102.49,409.43 1108.17,403.75 1166.19,403.75 1171.99,409.55 1171.99,439.03
CB_PMIC_1V2 on Bottom Layer "CB_PMIC_1V2_L06_P2772" (solid, remove dead copper, pour order 22400): 29 vertices, not listed, extent 707.63,498.65 1641,888.77
PMIC_1V8 on Bottom Layer "PMIC_1V8_L08_P22370" (solid, remove dead copper, pour order 22370): 1099.86,933.54 1091.01,924.7 1091.01,893.23 1095.57,888.66 1152.37,888.66 1157.8,894.1 1157.8,929.92 1154.17,933.54
CB_PMIC_1V8 on Bottom Layer "CB_PMIC_1V8_L08_P22373" (solid, remove dead copper, pour order 22373): 1676.96,917.7 1691.72,902.94 1691.72,882.98 1674.57,865.83 1652,865.83 1643.89,873.94 1643.89,889.9 1640.88,892.91 1551.72,892.91 1546.67,897.96 1546.67,910.96 1553.4,917.7
VCC_3V3 on Bottom Layer "TOP-No Net 1" (solid, remove dead copper, pour order 22381): 1934,869.76 1942,877.77 1992,877.77 1997,872.77 1997,791.77 1978,772.77 1943.09,772.76 1877.08,838.77 1777,838.77 1777,869.77
GND on Bottom Layer "TOP-No Net 1" (solid, remove dead copper, pour order 22404): 40 vertices, not listed, extent 1067,1495.77 2136,2495.77
RADAR_1V2 on Bottom Layer "RADAR_1V2_L08_P22392" (solid, remove dead copper, pour order 22392): 754.55,2073.69 785.72,2073.69 809.14,2050.28 809.14,1934.91 809.14,1850.72 794.58,1836.16 731.57,1836.16 711.56,1856.17 711.56,2047.83 663.95,2095.44 663.95,2239.83 675.76,2251.64 727.29,2251.64 743.43,2235.5 743.43,2084.81
VCC_LD_SW_3V3 on Bottom Layer "TOP-No Net 1" (solid, remove dead copper, pour order 22389): 27 vertices, not listed, extent 706.38,1214.77 857.38,1526.61
PMIC_1V0 on Bottom Layer "PMIC_1V0_L08_P22371" (solid, remove dead copper, pour order 22371): 867.14,885.3 867.14,877.83 887.51,857.46 897.27,857.46 928.35,888.54 942.68,888.54 958.89,904.75 958.89,919.08 953.02,924.96 920.83,924.96 910.1,914.23 896.08,914.23
no net on Bottom Layer "NONET_L08_P22363" (solid, remove dead copper, pour order 22363): 1569.79,301.45
CONN_5V on Bottom Layer "CONN_5V_L08_P22369" (solid, remove dead copper, pour order 22369): 18 vertices, not listed, extent 655.38,224.22 722.36,291.23
PMIC_3V3 on Bottom Layer "PMIC_3V3_L08_P22365" (solid, remove dead copper, pour order 22365): 21 vertices, not listed, extent 880.42,341.68 922.06,398.85
5V_IN_USB on Bottom Layer "5V_IN_USB_L08_P22377" (solid, remove dead copper, pour order 22377): 1731.34,109 1713.45,109 1674.16,69.71 1674.16,41.53 1682.02,33.67 1755.45,33.67 1775.51,53.72 1775.51,75.13 1768.19,82.45 1757.89,82.45
GND on Bottom Layer "GND_L08_P22367" (solid, remove dead copper, pour order 22367): 1014,494.86 996.95,494.86 975.37,473.28 975.37,444.38 981.34,438.4 981.72,438.78 1020.45,438.78 1027.2,445.53 1027.2,481.66
CB_PMIC_1V8 on Bottom Layer "CB_PMIC_1V8_L08_P22385" (solid, remove dead copper, pour order 22385): 19 vertices, not listed, extent 981.49,1022.46 1194.59,1147.7
RADAR_1V8 on Bottom Layer "RADAR_1V8_L08_P22384" (solid, remove dead copper, pour order 22384): 1110.72,1078.67 1062.54,1078.67 1056.85,1072.98 1056.85,1056.17 1027.33,1026.64 1027.33,798.64 1038.81,787.16 1074.08,787.16 1083.1,796.18 1083.1,924.53 1095.81,937.25 1095.81,1022.42 1115.45,1042.06 1115.45,1073.94
GND on Bottom Layer "GND_L06_P444" (solid, remove dead copper, pour order 22390): 20 vertices, not listed, extent 830.07,1770.77 1062,2011.99
CB_PMIC_1V0 on Bottom Layer "CB_PMIC_1V0_L06_P424" (solid, remove dead copper, pour order 22387): 524.94,1916.45 644.31,1916.45 653.59,1907.17 653.59,1899.89 649.32,1895.62 584.79,1895.62 558.17,1869 558.17,1751.32 534.31,1727.46 527.81,1720.96 449.72,1720.96 433.6,1737.08 433.6,1825.11
no net on Bottom Layer "NONET_L08_P22364" (solid, remove dead copper, pour order 22364): 804.19,1447.49
GND on Bottom Layer "GND_L08_P22374" (solid, remove dead copper, pour order 22374): 975.14,885.49 975.14,791.56 992.74,773.96 1006.27,773.96 1025.86,793.55 1025.86,836.25 1006.22,855.89 1006.22,886.59 1002.29,890.51 980.16,890.51
PMIC_1V2 on Bottom Layer "PMIC_1V2_L08_P22383" (solid, remove dead copper, pour order 22383): 19 vertices, not listed, extent 715.91,706.62 836.99,866.88
CB_PMIC_1V0 on Bottom Layer "CB_PMIC_1V0_L06_P2768" (solid, remove dead copper, pour order 22379): 1547.22,849.77 1642,849.77 1652,839.77 1652,759.17 1628.7,735.86 1570.39,735.87 1547.22,759.03
CB_PMIC_1V2 on Bottom Layer "CB_PMIC_1V2_L08_P22382" (solid, remove dead copper, pour order 22382): 657.3,2079.8 621.09,2079.8 575.28,2125.61 575.28,2243.46 590.27,2258.45 655.63,2258.45 669.8,2244.28 669.8,2092.3
VCC_3V3 on Bottom Layer "VCC_3V3_L08_P22372" (solid, remove dead copper, pour order 22372): 465.74,1341.47 458.09,1333.82 458.09,1318.12 465.84,1310.37 575.16,1310.37 575.16,1341.47
PMIC_1V0 on Bottom Layer "PMIC_1V0_L06_P428" (solid, remove dead copper, pour order 22388): 692.97,1911.75 668.78,1935.95 610.68,1935.95 564.38,1889.65 564.38,1747.93 572.02,1740.29 577.52,1734.79 648.96,1734.79 692.97,1778.81
RADAR_1P0_RF1 on Bottom Layer "TOP-No Net 1" (solid, remove dead copper, pour order 22394): 31 vertices, not listed, extent 983.95,1668.77 1196.71,2126.01
GND on Bottom Layer "TOP-No Net 1" (solid, remove dead copper, pour order 22402): 215,549.77 30,549.95 30,2673.77 30.99,2674.77 240,2674.77 240,1678.77 205,1643.77 205,1285.63 170,1250.63 170,764.77 215,719.77
GND on Bottom Layer "GND_L06_P430" (solid, remove dead copper, pour order 22378): 1038.15,1421.41 1129.36,1421.4 1187.99,1362.77 1209,1362.77 1213,1358.77 1213,1337.77 1189,1313.77 1166.99,1313.77 1154,1326.77 1154,1355.77 1117,1392.77 1038.15,1392.77
RADAR_1V8 on Bottom Layer "BOTTOM-AR_1V8" (solid, remove dead copper, pour order 22375): 1170.02,1724.77 1128.74,1724.77 1121.59,1731.91 1121.59,1823.9 1170.02,1823.9 1170.02,1738.5
RADAR_1V8 on Bottom Layer "BOTTOM-AR_1V8" (solid, remove dead copper, pour order 22376): 1170.02,1724.77 1128.74,1724.77 1121.59,1731.91 1121.59,1823.9 1170.02,1823.9 1170.02,1738.5
RADAR_1P0_RF2 on Bottom Layer "TOP-No Net 1" (solid, remove dead copper, pour order 22393): 1275,2236.36 1237.61,2273.75 1183.37,2273.75 1176.26,2280.86 1176.26,2335.39 1187.07,2346.2 1305.72,2346.2 1344.74,2307.18 1344.74,2257.3 1344.74,1978.78 1344.74,1733.51 1332,1720.77 1281,1720.77 1275,1726.77 1275,1903.28
GND on Bottom Layer "RADAR_1V8_L01_P-001" (solid, remove dead copper, pour order 22401): 20 vertices, not listed, extent 846.86,1982.77 1620,2522.77
RADAR_VOUT_PA on Bottom Layer "TOP-No Net 1" (solid, remove dead copper, pour order 22386): 1460.59,1984.77 1485.59,1959.77 1485.59,1744.77 1470.59,1729.77 1430.59,1729.77 1421.27,1739.09 1421.27,1874.09 1379.05,1916.31 1366.52,1916.31 1360.59,1922.24 1360.59,1974.77 1370.59,1984.77
no net on Top Solder "Top Solder-No Net" (solid, pour order 22405): 91 vertices, not listed, extent 801.83,1547.77 1994,2673.77
no net on Bottom Solder "RADAR_1V8_L01_P-001" (solid, pour order 22406): 40 vertices, not listed, extent 1068,1503.77 1955,2540.64
RADAR_1V2 on L4_SIGNAL 2 "RADAR_1V2_L04_P22346" (solid, remove dead copper, pour order 22346): 822.06,1407.56 822.06,1334.62 843.25,1313.43 1131.97,1313.43 1161.23,1342.69 1161.23,1378.15 1145.47,1393.91 980.65,1393.91 955.71,1418.85 833.34,1418.85
CONN_5V on L4_SIGNAL 2 "CONN_5V_L04_P22347" (solid, remove dead copper, pour order 22347): 1557.91,206.68 1632.96,281.73 1632.96,473.15 1699.98,540.16 1699.98,633.33 1655.46,677.84 1570.98,677.84 1539.71,646.57 1539.71,580.18 1512.82,553.3 1512.82,501.18 1388.84,377.19 1388.84,260.66 1442.82,206.68
PMIC_1V8 on L4_SIGNAL 2 "PMIC_1V8_L04_P22352" (solid, remove dead copper, pour order 22352): 1190.32,988.26 1444.87,733.71 1444.87,695.63 1444.87,666.41 1341.68,563.22 1168.38,563.22 1037.34,694.26 980.94,694.26 948.61,726.59 948.61,852.92 969.45,873.76 969.45,922.63 1035.08,988.26
VCC_LD_SW_3V3 on L4_SIGNAL 2 "VCC_LD_SW_3V3_L04_P22351" (solid, remove dead copper, pour order 22351): 744.07,847.29 810.9,847.29 834.96,823.23 914.62,823.23 973.64,882.25 973.64,940.71 1054.79,1021.86 1054.79,1186.26 941.47,1299.58 805.83,1299.58 796.73,1308.67 724.81,1308.67 706.94,1290.8 706.94,884.42
GND on L4_SIGNAL 2 "GND_L04_P22354" (solid, remove dead copper, pour order 22354): 43 vertices, not listed, extent 27.54,0.62 1373.87,1426.04
5V_IN on L4_SIGNAL 2 "5V_IN_L04_P22348" (solid, remove dead copper, pour order 22348): 26 vertices, not listed, extent 117.66,36.19 740.38,354.66
5V_IN on L4_SIGNAL 2 "5V_IN_L04_P22353" (solid, remove dead copper, pour order 22353): 1546.44,187.64 1618.34,259.54 1633.81,275.01 1633.81,463.09 1732.85,562.13 1785.69,562.13 1979.55,368.27 1979.55,90.38 1915.58,26.41 1599.92,26.41 1546.44,79.9
PMIC_1V2 on L4_SIGNAL 2 "PMIC_1V2_L04_P22350" (solid, remove dead copper, pour order 22350): 19 vertices, not listed, extent 680.92,356.05 1256.36,825.17
CB_PMIC_1V0 on L4_SIGNAL 2 "CB_PMIC_1V0_L04_P22349" (solid, remove dead copper, pour order 22349): 451.41,2100.76 587.53,2100.76 645.98,2159.21 767.26,2159.21 828.79,2097.69 828.79,1930.93 758.81,1860.96 609.62,1860.96 564.02,1815.35 564.02,1760.44 528.14,1724.56 427.39,1724.56 400.94,1751.01 400.94,2050.28
VCC_3V3 on L4_SIGNAL 2 "VCC_3V3_L04_P22344" (solid, remove dead copper, pour order 22344): 832.32,388.21 832.32,360.68 838.39,354.61 872.23,354.61 878.54,360.92 878.54,369.6 850.83,397.31 841.42,397.31
PMIC_3V3 on L4_SIGNAL 2 "PMIC_3V3_L04_P22345" (solid, remove dead copper, pour order 22345): 17 vertices, not listed, extent 845.88,328.93 956.25,562.61
CB_PMIC_1V0 on L6_SIGNAL 4 "CB_PMIC_1V0_L06_P22361" (solid, remove dead copper, pour order 22361): 24 vertices, not listed, extent 397.55,764.37 1780.59,2159.74
PMICOUT_3V3 on L6_SIGNAL 4 "PMICOUT_3V3_L06_P22362" (solid, remove dead copper, pour order 22362): 21 vertices, not listed, extent 371.49,308 2157.3,2544.82
CONN_5V on L6_SIGNAL 4 "CONN_5V_L06_P22357" (solid, remove dead copper, pour order 22357): 19 vertices, not listed, extent 705.14,24.84 1414.33,613.24
5V_IN on L6_SIGNAL 4 "5V_IN_L06_P22360" (solid, remove dead copper, pour order 22360): 27 vertices, not listed, extent 64.48,24.54 1090.38,1519.31
PMIC_1V0 on L6_SIGNAL 4 "PMIC_1V0_L06_P22359" (solid, remove dead copper, pour order 22359): 21 vertices, not listed, extent 554.78,820.57 961.17,1825.38
RADAR_1V8 on L6_SIGNAL 4 "RADAR_1V8_L06_P22358" (solid, remove dead copper, pour order 22358): 23 vertices, not listed, extent 819.33,891.76 1255.75,1729.37
PMICVIO_3V3 on L6_SIGNAL 4 "PMICVIO_3V3_L06_P22355" (solid, remove dead copper, pour order 22355): 17 vertices, not listed, extent 772.65,527.9 1190.94,796.84
VCC_3V3 on L6_SIGNAL 4 "VCC_3V3_L06_P22356" (solid, remove dead copper, pour order 22356): 347.25,1338.04 376.25,1309.04 476.08,1309.04 513.25,1346.21 513.25,1695.32 492.85,1715.72 442.01,1715.72 366.66,1791.07 258.62,1791.07 236.54,1768.99 236.54,1577.59 347.25,1466.88
GND on L2_GND "GND_L02_P226" (hatched 90Degree grid 5 track 8, remove dead copper, pour order 22324): 35,2669.77 2135.01,2669.77 2135,31.71 34.99,31.71
GND on L7_GND "TOP-No Net 1" (solid, remove dead copper, pour order 22343): 0,2677.16 2165.35,2677.15 2165.35,0 0,0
